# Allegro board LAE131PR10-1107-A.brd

Outline 326.8 x 119.05 mm; copper layers: TOP, GND1, IN1, VCC, IN2, IN3, GND2, BOTTOM. Coordinates in mm from the lower left corner of the outline.

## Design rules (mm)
constraint set DEFAULT: min track width 0.102
net group BC BUS_12/15: nets BC_CLK_ECE1117 BC_DAT_ECE1117
net group CLK_ITPXDP__R: nets CLK_ITPXDP_N_R CLK_ITPXDP_P_R
net group CODEC-SENSE_10: nets AUD_HP_NB_SENSE AUD_SENSE_A
net group CPU_DP1_0_C: nets CPU_DP1_N0_C CPU_DP1_P0_C
net group CPU_DP1_1_C: nets CPU_DP1_N1_C CPU_DP1_P1_C
net group CPU_DP1_2_C: nets CPU_DP1_N2_C CPU_DP1_P2_C
net group CPU_DP1_3_C: nets CPU_DP1_N3_C CPU_DP1_P3_C
net group CPU_DP1_AUX_C: nets CPU_DP1_AUXN_C CPU_DP1_AUXP_C
net group CPU_DP3_AUXN: nets CPU_DP3_AUXN CPU_DP3_AUXP
net group DIFFPAIR20: nets USB20_N2_R USB20_P2_R
net group DIFFPAIR23: nets TBT_I2C_SCL TBT_I2C_SDA
net group DIFFPAIR24: nets TBTA_LSRX_R TBTA_LSTX_R
net group DIFFPAIR25: nets TBTA_LSRX TBTA_LSTX
net group EDP_TX2: nets EDP_TXN2 EDP_TXP2
net group EDP_TX2_C: nets EDP_TXN2_C EDP_TXP2_C
net group EDP_TX3: nets EDP_TXN3 EDP_TXP3
net group EDP_TX3_C: nets EDP_TXN3_C EDP_TXP3_C
net group HDMI_12_15: nets CPU_DP1_AUXN CPU_DP1_AUXP
net group ISUMN_GT: nets ISUMN_GT ISUMP_GT
net group ISUMN_IA: nets ISUMN_IA ISUMP_IA
net group MSDATA: nets MSCLK MSDATA
net group PCIE_PRX_C_DTX_5: nets PCIE_PRX_C_DTX_N5 PCIE_PRX_C_DTX_P5
net group PCIE_PRX_C_DTX_6: nets PCIE_PRX_C_DTX_N6 PCIE_PRX_C_DTX_P6
net group PCIE_PRX_C_DTX_7: nets PCIE_PRX_C_DTX_N7 PCIE_PRX_C_DTX_P7
net group PCIE_PRX_C_DTX_8: nets PCIE_PRX_C_DTX_N8 PCIE_PRX_C_DTX_P8
net group PCIE_PRX_DTX_4: nets PCIE_PRX_DTX_N4 PCIE_PRX_DTX_P4
net group PCIE_PRX_DTX_7: nets PCIE_PRX_DTX_N7 PCIE_PRX_DTX_P7
net group PCIE_PRX_DTX_8: nets PCIE_PRX_DTX_N8 PCIE_PRX_DTX_P8
net group PCIE_PTX_C_DRX_4: nets PCIE_PTX_C_DRX_N4 PCIE_PTX_C_DRX_P4
net group PCIE_PTX_C_DRX_7: nets PCIE_PTX_C_DRX_N7 PCIE_PTX_C_DRX_P7
net group PCIE_PTX_C_DRX_8: nets PCIE_PTX_C_DRX_N8 PCIE_PTX_C_DRX_P8
net group PCIE_PTX_DRX_4: nets PCIE_PTX_DRX_N4 PCIE_PTX_DRX_P4
net group PCIE_PTX_DRX_7: nets PCIE_PTX_DRX_N7 PCIE_PTX_DRX_P7
net group PCIE_PTX_DRX_8: nets PCIE_PTX_DRX_N8 PCIE_PTX_DRX_P8
net group PCIE_RCOMP: nets PCIE_RCOMPN PCIE_RCOMPP
net group SATA_12: nets PCIE_PRX_DTX_P11 PCIE_PRX_DTX_P12
net group SD/MMCDAT0/RCLK+_R: nets SD/MMCDAT0/RCLK+_R SD/MMCDAT1/RCLK-_R
net group TBTA_AUX: nets TBTA_AUXN TBTA_AUXP
net group TBTA_AUX_C: nets TBTA_AUXN_C TBTA_AUXP_C
net group TBTA_USB20_: nets TBTA_USB20_N TBTA_USB20_P
net group USB3_PRX_L_DTX_2: nets USB3_PRX_L_DTX_N2 USB3_PRX_L_DTX_P2
net group USB3_PTX_L_DRX_2: nets USB3_PTX_L_DRX_N2 USB3_PTX_L_DRX_P2
net group USB20_4_L: nets USB20_N4_L USB20_P4_L
net group USB20_5_R: nets USB20_N5_R USB20_P5_R
net group USB20_7_L: nets USB20_N7_L USB20_P7_L
net group USB20_8_R: nets USB20_N8_R USB20_P8_R
net group VSA_SEN+: nets VSA_SEN+ VSA_SEN-
net group AR DDI_12_15: nets CPU_DP1_N0 CPU_DP1_N1 CPU_DP1_N2 CPU_DP1_N3 CPU_DP1_P0 CPU_DP1_P1 CPU_DP1_P2 CPU_DP1_P3
net group AR TBT: nets TBTA_HPD
net group AR TBT90H: nets TBTA_RX1N TBTA_RX1P TBTA_RX2N TBTA_RX2P TBTA_TX1N TBTA_TX1N_C TBTA_TX1P TBTA_TX1P_C TBTA_TX2N TBTA_TX2N_C TBTA_TX2P TBTA_TX2P_C
net group AR-HDMI: nets AR_DP1_N0 AR_DP1_N1 AR_DP1_N2 AR_DP1_N3 AR_DP1_P0 AR_DP1_P1 AR_DP1_P2 AR_DP1_P3 HDMI_CLKN HDMI_CLKP HDMI_L_CLKN HDMI_L_CLKP HDMI_L_TX_N0 HDMI_L_TX_N1 HDMI_L_TX_N2 HDMI_L_TX_P0 HDMI_L_TX_P1 HDMI_L_TX_P2 HDMI_TX_N0 HDMI_TX_N1 HDMI_TX_N2 HDMI_TX_P0 HDMI_TX_P1 HDMI_TX_P2
net group ASYN-COMP: nets CFG_RCOMP CPU_POPIRCOMP EDP_COMP EDRAM_OPIO_RCOMP EMMC_RCOMP EOPIO_RCOMP PCH_POPIRCOMP SD_RCOMP SM_RCOMP0 SM_RCOMP1 SM_RCOMP2 USBCOMP
net group ASYN_12: nets H_CATERR# H_CPUPWRGD H_CPUPWRGD_R H_PROCHOT# H_PROCHOT#_R H_THERMTRIP# H_VCCST_PWRGD_XDP PCH_PLTRST# PCH_PLTRST#_5105 PCH_PLTRST#_AND PCH_PLTRST#_EC PECI_EC PECI_EC_R PLTRST_LAN# PLTRST_TPM# THERMATRIP2# VCCST_PWRGD XDP_OBS0 XDP_OBS0_R XDP_OBS1 XDP_OBS1_R XDP_OBS2_R
net group ASYN_20: nets +DDR_VREF_A_DQ +DDR_VREF_B_DQ +DDR_VREF_CA DDR_DRAMRST# DDR_DRAMRST#_R
net group CARD-S_12: nets SD/MMCCD# SD/MMCCLK SD/MMCCLK_R SD/MMCCMD SD/MMCCMD_R SD/MMCDAT2 SD/MMCDAT2_R SD/MMCDAT3 SD/MMCDAT3_R SDWP
net group CARD_20: nets SD/MMCDAT0/RCLK+ SD/MMCDAT1/RCLK- SD_UHS2_D0N SD_UHS2_D0P SD_UHS2_D1N SD_UHS2_D1P
net group CLK-S_15: nets CLKREQ_PCIE#0 CPU_XDP_TCLK DMIC_CLK0 DMIC_CLK_CODEC HDA_BIT_CLK HDA_BIT_CLK_R JTAG_CLK PCH_JTAG_TCK PCI_CLK_LPC1 SUSCLK SUSCLK_R WIGIG_32KHZ XCLK_BIASREF XDP_JTAGX
net group CLK_ITPXDP_N: nets CLK_ITPXDP_P
net group CODEC-HP_10: nets AUD_HP_OUT_L AUD_HP_OUT_L1 AUD_HP_OUT_R AUD_HP_OUT_R1
net group CODEC_10: nets RING2 RING2_R SLEEVE SLEEVE_R
net group CONTROL LINK SIGNAL: nets PCH_CL_CLK1 PCH_CL_DATA1 PCH_CL_RST1#
net group CRITICAL S_15: nets INTRUDER# PCH_DPWROK PCH_PCIE_WAKE# PCH_PWROK PCH_RSMRST# PCIE_WAKE# PCIE_WAKE#_R SIO_PWRBTN# SIO_RCIN# SIO_RCIN#_EC SYS_RESET# SYS_RESET#_R
net group DDR-ALERT: nets DDR_A_ALERT#
net group DDRA-CLK: nets DDR_A_CLK0 DDR_A_CLK1 DDR_A_CLK#0 DDR_A_CLK#1
net group DDRA-CMD: nets DDR_A_ACT# DDR_A_BA0 DDR_A_BA1 DDR_A_BG0 DDR_A_BG1 DDR_A_MA0 DDR_A_MA1 DDR_A_MA2 DDR_A_MA3 DDR_A_MA4 DDR_A_MA5 DDR_A_MA6 DDR_A_MA7 DDR_A_MA8 DDR_A_MA9 DDR_A_MA10 DDR_A_MA11 DDR_A_MA12 DDR_A_MA13 DDR_A_MA14 DDR_A_MA15 DDR_A_MA16 DDR_A_PARITY
net group DDRA-CTL: nets DDR_A_CS#0 DDR_A_CS#1 DDR_A_ODT0 DDR_A_ODT1
net group DDRA-D0: nets DDR_A_D0 DDR_A_D1 DDR_A_D2 DDR_A_D3 DDR_A_D4 DDR_A_D5 DDR_A_D6 DDR_A_D7
net group DDRA-D1: nets DDR_A_D8 DDR_A_D9 DDR_A_D10 DDR_A_D11 DDR_A_D12 DDR_A_D13 DDR_A_D14 DDR_A_D15
net group DDRA-D2: nets DDR_A_D16 DDR_A_D17 DDR_A_D18 DDR_A_D19 DDR_A_D20 DDR_A_D21 DDR_A_D22 DDR_A_D23
net group DDRA-D3: nets DDR_A_D24 DDR_A_D25 DDR_A_D26 DDR_A_D27 DDR_A_D28 DDR_A_D29 DDR_A_D30 DDR_A_D31
net group DDRA-D4: nets DDR_A_D32 DDR_A_D33 DDR_A_D34 DDR_A_D35 DDR_A_D36 DDR_A_D37 DDR_A_D38 DDR_A_D39
net group DDRA-D5: nets DDR_A_D40 DDR_A_D41 DDR_A_D42 DDR_A_D43 DDR_A_D44 DDR_A_D45 DDR_A_D46 DDR_A_D47
net group DDRA-D6: nets DDR_A_D48 DDR_A_D49 DDR_A_D50 DDR_A_D51 DDR_A_D52 DDR_A_D53 DDR_A_D54 DDR_A_D55
net group DDRA-D7: nets DDR_A_D56 DDR_A_D57 DDR_A_D58 DDR_A_D59 DDR_A_D60 DDR_A_D61 DDR_A_D62 DDR_A_D63
net group DDRA-DQS: nets DDR_A_DQS0 DDR_A_DQS1 DDR_A_DQS2 DDR_A_DQS3 DDR_A_DQS4 DDR_A_DQS5 DDR_A_DQS6 DDR_A_DQS7 DDR_A_DQS#0 DDR_A_DQS#1 DDR_A_DQS#2 DDR_A_DQS#3 DDR_A_DQS#4 DDR_A_DQS#5 DDR_A_DQS#6 DDR_A_DQS#7
net group DDRA_CKE: nets DDR_A_CKE0 DDR_A_CKE1 DDR_A_CKE2 DDR_A_CKE3
net group DDRB-CLK: nets DDR_B_CLK0 DDR_B_CLK1 DDR_B_CLK#0 DDR_B_CLK#1
net group DDRB-CMD: nets DDR_B_ACT# DDR_B_BA0 DDR_B_BA1 DDR_B_BG0 DDR_B_BG1 DDR_B_MA0 DDR_B_MA1 DDR_B_MA2 DDR_B_MA3 DDR_B_MA4 DDR_B_MA5 DDR_B_MA6 DDR_B_MA7 DDR_B_MA8 DDR_B_MA9 DDR_B_MA10 DDR_B_MA11 DDR_B_MA12 DDR_B_MA13 DDR_B_MA14 DDR_B_MA15 DDR_B_MA16 DDR_B_PARITY
net group DDRB-CTL: nets DDR_B_CS#0 DDR_B_CS#1 DDR_B_ODT0 DDR_B_ODT1
net group DDRB-D0: nets DDR_B_D0 DDR_B_D1 DDR_B_D2 DDR_B_D3 DDR_B_D4 DDR_B_D5 DDR_B_D6 DDR_B_D7
net group DDRB-D1: nets DDR_B_D8 DDR_B_D9 DDR_B_D10 DDR_B_D11 DDR_B_D12 DDR_B_D13 DDR_B_D14 DDR_B_D15
net group DDRB-D2: nets DDR_B_D16 DDR_B_D17 DDR_B_D18 DDR_B_D19 DDR_B_D20 DDR_B_D21 DDR_B_D22 DDR_B_D23
net group DDRB-D3: nets DDR_B_D24 DDR_B_D25 DDR_B_D26 DDR_B_D27 DDR_B_D28 DDR_B_D29 DDR_B_D30 DDR_B_D31
net group DDRB-D4: nets DDR_B_D32 DDR_B_D33 DDR_B_D34 DDR_B_D35 DDR_B_D36 DDR_B_D37 DDR_B_D38 DDR_B_D39
net group DDRB-D5: nets DDR_B_D40 DDR_B_D41 DDR_B_D42 DDR_B_D43 DDR_B_D44 DDR_B_D45 DDR_B_D46 DDR_B_D47
net group DDRB-D6: nets DDR_B_D48 DDR_B_D49 DDR_B_D50 DDR_B_D51 DDR_B_D52 DDR_B_D53 DDR_B_D54 DDR_B_D55
net group DDRB-D7: nets DDR_B_D56 DDR_B_D57 DDR_B_D58 DDR_B_D59 DDR_B_D60 DDR_B_D61 DDR_B_D62 DDR_B_D63
net group DDRB-DQS: nets DDR_B_DQS0 DDR_B_DQS1 DDR_B_DQS2 DDR_B_DQS3 DDR_B_DQS4 DDR_B_DQS5 DDR_B_DQS6 DDR_B_DQS7 DDR_B_DQS#0 DDR_B_DQS#1 DDR_B_DQS#2 DDR_B_DQS#3 DDR_B_DQS#4 DDR_B_DQS#5 DDR_B_DQS#6 DDR_B_DQS#7
net group DDRB_ALERT: nets DDR_B_ALERT#
net group DDRB_CKE: nets DDR_B_CKE0 DDR_B_CKE1 DDR_B_CKE2 DDR_B_CKE3
net group DP-DDI2_15: nets CPU_DP2_AUXN CPU_DP2_AUXN_C CPU_DP2_AUXP CPU_DP2_AUXP_C CPU_DP2_N0 CPU_DP2_N0_C CPU_DP2_N1 CPU_DP2_N1_C CPU_DP2_N2 CPU_DP2_N2_C CPU_DP2_N3 CPU_DP2_N3_C CPU_DP2_P0 CPU_DP2_P0_C CPU_DP2_P1 CPU_DP2_P1_C CPU_DP2_P2 CPU_DP2_P2_C CPU_DP2_P3 CPU_DP2_P3_C SW2_DP1_AUXN SW2_DP1_AUXN_C SW2_DP1_AUXP SW2_DP1_AUXP_C SW2_DP1_N0 SW2_DP1_N0_C SW2_DP1_N1 SW2_DP1_N1_C SW2_DP1_N2 SW2_DP1_N2_C SW2_DP1_N3 SW2_DP1_N3_C SW2_DP1_P0 SW2_DP1_P0_C SW2_DP1_P1 SW2_DP1_P1_C SW2_DP1_P2 SW2_DP1_P2_C SW2_DP1_P3 SW2_DP1_P3_C SW2_DP2_AUXN SW2_DP2_AUXN_C SW2_DP2_AUXP SW2_DP2_AUXP_C SW2_DP2_N0 SW2_DP2_N0_C SW2_DP2_N1 SW2_DP2_N1_C SW2_DP2_N2 SW2_DP2_N2_C SW2_DP2_N3 SW2_DP2_N3_C SW2_DP2_P0 SW2_DP2_P0_C SW2_DP2_P1 SW2_DP2_P1_C SW2_DP2_P2 SW2_DP2_P2_C SW2_DP2_P3 SW2_DP2_P3_C
net group EDP_15: nets EDP_AUXN EDP_AUXN_C EDP_AUXP EDP_AUXP_C EDP_TXN0 EDP_TXN0_C EDP_TXN1 EDP_TXN1_C EDP_TXP0 EDP_TXP0_C EDP_TXP1 EDP_TXP1_C
net group EMC_50H: nets CORE_SNUB CORE_SW FAN1_PWM FAN1_TACH LX_1.8VALW LX_1V_PRIM LX_1VS_VCCIO LX_VCC_EDRAM LX_VCC_EOPIO SNUB_1.8VALW SNUB_1V_PRIM SNUB_1VS_VCCIO SNUB_VCC_EDRAM SNUB_VCC_EOPIO
net group EMI: nets BIA_PWM BIA_PWM_EC BST_3V BST_5V CLKRUN# EDP_BIA_PWM HOST_DEBUG_TX TP_LAN_JTAG_TCK
net group ESD-GND: nets CPU_XDP_PRDY# CPU_XDP_PREQ# CPU_XDP_TDI CPU_XDP_TDO CPU_XDP_TMS CPU_XDP_TRST# ME_RESET# PCH_JTAG_TDI PCH_JTAG_TDO PCH_JTAG_TMS POWER_SW#_MB POWER_SW_IN# RUNPWROK SIO_SLP_A# XDP_DBRESET#
net group ESD-NOCROSS-MOAT: nets CFG0 CFG1 CFG2 CFG3 CFG4 CFG5 CFG6 CFG7 CFG8 CFG9 CFG10 CFG11 CFG12 CFG13 CFG14 CFG15 CFG16 CFG17 CFG18 CFG19 ITP_PMODE SIO_EXT_SMI# USB_OC3#
net group ESPI: nets ESPI_ALERT# ESPI_CLK ESPI_CLK_5105 ESPI_CS# ESPI_IO0 ESPI_IO0_R ESPI_IO1 ESPI_IO1_R ESPI_IO2 ESPI_IO2_R ESPI_IO3 ESPI_IO3_R ESPI_RESET# SLOT2_CONFIG_0 SLOT2_CONFIG_1 SLOT2_CONFIG_2 SLOT2_CONFIG_3
net group GREENCLK_20: nets MEC_XTAL1 MEC_XTAL2 MEC_XTAL2_R PCH_RTCRST# PCH_RTCX1 PCH_RTCX2 PCH_RTCX2_R SRTCRST# XTAL24_IN XTAL_25_IN XTAL_25_OUT XTAL_25_OUT_R XTALO_R
net group HDA_5_15: nets DMIC0 HDA_RST# HDA_RST#_R HDA_SDIN0 HDA_SDIN0_R HDA_SDOUT HDA_SDOUT_R HDA_SYNC HDA_SYNC_R
net group I2C_15: nets ISH_I2C2_SCL ISH_I2C2_SCL_R ISH_I2C2_SDA ISH_I2C2_SDA_R
net group MDI_20: nets LAN_MDIN0 LAN_MDIN0_L LAN_MDIN1 LAN_MDIN1_L LAN_MDIN2 LAN_MDIN2_L LAN_MDIN3 LAN_MDIN3_L LAN_MDIP0 LAN_MDIP0_L LAN_MDIP1 LAN_MDIP1_L LAN_MDIP2 LAN_MDIP2_L LAN_MDIP3 LAN_MDIP3_L
net group PCIE_12: nets PCIE_PRX_C_DTX_N1 PCIE_PRX_C_DTX_N9 PCIE_PRX_C_DTX_P1 PCIE_PRX_C_DTX_P9 PCIE_PRX_DTX_N1 PCIE_PRX_DTX_N3 PCIE_PRX_DTX_N5 PCIE_PRX_DTX_N6 PCIE_PRX_DTX_N9 PCIE_PRX_DTX_N11 PCIE_PRX_DTX_N12 PCIE_PRX_DTX_P1 PCIE_PRX_DTX_P3 PCIE_PRX_DTX_P5 PCIE_PRX_DTX_P6 PCIE_PRX_DTX_P9 PCIE_PTX_C_DRX_N1 PCIE_PTX_C_DRX_N3 PCIE_PTX_C_DRX_N5 PCIE_PTX_C_DRX_N6 PCIE_PTX_C_DRX_N9 PCIE_PTX_C_DRX_N11 PCIE_PTX_C_DRX_N12 PCIE_PTX_C_DRX_P1 PCIE_PTX_C_DRX_P3 PCIE_PTX_C_DRX_P5 PCIE_PTX_C_DRX_P6 PCIE_PTX_C_DRX_P9 PCIE_PTX_C_DRX_P11 PCIE_PTX_C_DRX_P12 PCIE_PTX_DRX_N1 PCIE_PTX_DRX_N3 PCIE_PTX_DRX_N5 PCIE_PTX_DRX_N6 PCIE_PTX_DRX_N9 PCIE_PTX_DRX_N11 PCIE_PTX_DRX_N12 PCIE_PTX_DRX_P1 PCIE_PTX_DRX_P3 PCIE_PTX_DRX_P5 PCIE_PTX_DRX_P6 PCIE_PTX_DRX_P9 PCIE_PTX_DRX_P11 PCIE_PTX_DRX_P12
net group PLAT-CLK_12: nets CLK_ITPXDP_N CLK_PCIE_N0 CLK_PCIE_N1 CLK_PCIE_N2 CLK_PCIE_N3 CLK_PCIE_N4 CLK_PCIE_N5 CLK_PCIE_P0 CLK_PCIE_P1 CLK_PCIE_P2 CLK_PCIE_P3 CLK_PCIE_P4 CLK_PCIE_P5 CLKREQ_PCIE#1 CLKREQ_PCIE#2 CLKREQ_PCIE#3 CLKREQ_PCIE#4 CLKREQ_PCIE#5 XTAL24_OUT XTAL24_OUT_R
net group PWR_SRC: nets +PWR_SRC
net group RJ45_20: nets RJ45_MDIN0 RJ45_MDIN1 RJ45_MDIN2 RJ45_MDIN3 RJ45_MDIP0 RJ45_MDIP1 RJ45_MDIP2 RJ45_MDIP3
net group S20: nets +PWR_SRC_AC +SDC_IN TBTA_BOT_N TBTA_BOT_N_R TBTA_BOT_P TBTA_BOT_P_R TBTA_TOP_N TBTA_TOP_N_R TBTA_TOP_P TBTA_TOP_P_R XTALI XTALO
net group SD-NOCROSS-MOAT: nets JTAG_RST# ME_SUS_PWR_ACK SUSACK# USB_OC0# USB_OC1# USB_OC2#
net group SENSE_25: nets VCC_GT_SENSE VCCIO_SENSE VCCSENSE VSS_GT_SENSE VSSIO_SENSE VSSSENSE
net group SIM_15: nets UIM_CLK UIM_DATA UIM_RESET
net group SMB_15: nets CLK_TP_SIO_I2C_DAT CLK_TP_SIO_R CPU_DP1_CTRL_CLK CPU_DP1_CTRL_DATA CPU_DP2_CTRL_CLK CPU_DP2_CTRL_DATA DDR_XDP_WAN_SMBCLK DDR_XDP_WAN_SMBDAT HDMI_CTRL_CLK HDMI_CTRL_DATA MEM_SMBCLK MEM_SMBDATA PBAT_SMBCLK_C PBAT_SMBDAT_C SML0_SMBCLK SML0_SMBDATA SML1_SMBCLK SML1_SMBDATA USH_SMBCLK USH_SMBDAT
net group SPI-CLK_15: nets PCH_SPI_CLK PCH_SPI_CLK_0_R PCH_SPI_CLK_1_R PCH_SPI_CLK_2_R PCH_SPI_CLK_R1 TBT_ROM_CLK
net group SPI-S_5: nets PCH_SPI_CS#0 PCH_SPI_CS#0_R1 PCH_SPI_CS#0_R2 PCH_SPI_CS#1 PCH_SPI_CS#1_R1 PCH_SPI_CS#1_R2 PCH_SPI_CS#2 PCH_SPI_CS#2_R PCH_SPI_D0 PCH_SPI_D0_0_R PCH_SPI_D0_1_R PCH_SPI_D0_2_R PCH_SPI_D0_R1 PCH_SPI_D1 PCH_SPI_D1_0_R PCH_SPI_D1_1_R PCH_SPI_D1_2_R PCH_SPI_D1_R1 PCH_SPI_D2 PCH_SPI_D2_0_R PCH_SPI_D2_1_R PCH_SPI_D2_R1 PCH_SPI_D3 PCH_SPI_D3_0_R PCH_SPI_D3_1_R PCH_SPI_D3_R1 PCH_SPI_DO2_XDP PCH_SPI_DO_XDP RESET_OUT#_R
net group SPK_20: nets INT_SPK_L+ INT_SPK_L- INT_SPK_R+ INT_SPK_R- INT_SPKR_L+ INT_SPKR_L- INT_SPKR_R+ INT_SPKR_R-
net group SVID_12: nets H_CPU_SVIDALRT# VIDALERT_N VIDSCLK VIDSOUT
net group THERMAL_20: nets REM_DIODE1_N REM_DIODE1_P REM_DIODE2_N REM_DIODE2_P REM_DIODE4_N REM_DIODE4_P
net group USB20_12: nets SW_USB20_N1 SW_USB20_P1 USB20_N1 USB20_N1_R USB20_N2 USB20_N3 USB20_N3_R USB20_N4 USB20_N5 USB20_N7 USB20_N8 USB20_N10 USB20_P1 USB20_P1_R USB20_P2 USB20_P3 USB20_P3_R USB20_P4 USB20_P5 USB20_P7 USB20_P8 USB20_P10
net group USB30_12: nets USB3_PRX_DTX_N1 USB3_PRX_DTX_N2 USB3_PRX_DTX_N3 USB3_PRX_DTX_N4 USB3_PRX_DTX_P1 USB3_PRX_DTX_P2 USB3_PRX_DTX_P3 USB3_PRX_DTX_P4 USB3_PTX_C_DRX_N1 USB3_PTX_C_DRX_N2 USB3_PTX_C_DRX_N3 USB3_PTX_C_DRX_N4 USB3_PTX_C_DRX_P1 USB3_PTX_C_DRX_P2 USB3_PTX_C_DRX_P3 USB3_PTX_C_DRX_P4 USB3_PTX_DRX_N1 USB3_PTX_DRX_N2 USB3_PTX_DRX_N3 USB3_PTX_DRX_N4 USB3_PTX_DRX_P1 USB3_PTX_DRX_P2 USB3_PTX_DRX_P3 USB3_PTX_DRX_P4
net group W10: nets BAT1_LED# BAT2_LED# BATT_WHITE# BATT_YELLOW#
nets with their own width: min track width 0.203; nets TBTA_CC1 TBTA_CC2
nets with their own width: min track width 0.254; nets +1.0VO_DSW +3.3V_SPI +5V_ALWP +VCC_SA
nets with their own width: min track width 0.381; nets +SDREG2 HP_OUT_L HP_OUT_R
nets with their own width: min track width 0.508; nets +0.9V_LAN +1.0V_AMPHYPLL +1.0V_APLL +1.0V_APLLEBB +1.0V_CLK1 +1.0V_CLK2 +1.0V_CLK3 +1.0V_CLK4 +1.0V_CLK5 +1.0V_CLK6 +1.0V_DTS +1.0V_MPHYAON +1.0V_PRIM +1.0V_PRIM_CORE +1.0V_PRIM_XDP +1.0V_VCCST +1.0V_VCCST_C +1.0V_VCCSTG +1.2V_LDO +1.8V_RUN_CARD +3.3V_ALW +3.3V_ALW2 +3.3V_ALW_DSW +3.3V_ALW_UE1 +3.3V_ALWP +3.3V_CAM +3.3V_RTC_LDO +3.3V_RUN +3.3V_RUN_AUDIO +3.3V_RUN_UZ3 +3.3V_TP +5V_ALW +5V_ALW2 +COINCELL +DC_IN +DC_IN_SS +DDR_VREF_A_CA +PBATT +PECI_VREF +RSVD_VCC3P3_1 +RTC_CELL +RTC_CELL_VBAT +SIM_PWR +VCC_CORE +VCC_CORE_G0 +VCC_CORE_G1 +VCC_GT +VCHGR +VDDA_AVDD1 +VR_CAP +Z4012 GND GNDA Z2805 Z2806 Z2807 Z2808
nets with their own width: min track width 0.762; nets +1.0V_SRAM +3.3V_LAN_OUT
nets with their own width: min track width 1.016; nets +1.0VS_VCCIO +1.8V_PGPPF +1.8V_PRIM +3.3V_1.8V_PGPPG +3.3V_ALW_PCH +3.3V_LAN +3.3V_LAN_UZ2 +3.3V_PGPPB +3.3V_PGPPC +3.3V_PGPPD +3.3V_PGPPE +3.3V_RUN_CARD +5V_RUN_AUDIO +5V_TSP +GND_CHASSIS
nets with their own width: min track width 1.27; nets +3.3V_MMI_IN
nets with their own width: min track width 1.524; nets +3.3V_1.8V_PGPPA +EDP_VDD +LCDVDD
nets with their own width: min track width 2.032; nets +1.0V_MPHYGT +3.3V_WLAN +3.3V_WWAN_UZ4 +5V_RUN +BL_PWR_SRC +VHDMI_VCC
nets with their own width: min track width 2.54; nets +3.3V_WWAN +5V_USB_CHG_PWR

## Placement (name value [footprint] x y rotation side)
CA1  -  [C_0402]  304.97 21.51 270 top
CA2  -  [C_0402]  305.5 14.46 270 top
CA3  -  [C_0402]  305.53 16.15 90 top
CA4  -  [C_0402]  305.02 18.87 270 top
CA5  -  [C_0402]  62.11 115.09 0 top
CA6  -  [C_0402]  58.99 115.09 0 top
CA7  -  [C_0201]  56.31 110.22 0 top
CA8  -  [C_0201]  305.41 27.78 0 top
CA9  -  [C_0603]  304.5 26.83 0 top
CA10  -  [C_0201]  295.28 35.4 180 top
CA12  -  [C_0402]  309.6 21.53 0 top
CA13  -  [C_0402]  310.49 18.61 180 top
CA19  -  [C_0402]  295.91 9.7 0 top
CA22  -  [C_0402]  300.94 9.67 0 top
CA23  -  [C_0402]  299.79 9.66 180 top
CA24  -  [C_0402]  294.76 9.68 180 top
CA25  -  [C_0603]  300.67 27.29 270 top
CA27  -  [C_0402]  296.61 26.1 0 top
CA28  -  [C_0402]  296.61 25.22 0 top
CA29  -  [C_0603]  306.71 36.8 180 top
CA31  -  [C_0603]  294.26 38.45 90 top
CA33  -  [C_0402]  293.33 32.61 180 top
CA35  -  [C_0402]  305.63 30.7 0 top
CA41  -  [C_0402]  297.11 27.96 270 top
CA43  -  [C_0603]  303.35 27.51 270 top
CA44  -  [C_0603]  302.14 27.51 270 top
CA45  -  [C_0201]  300.98 38 0 top
CA46  -  [C_0603]  301.12 39.21 90 top
CA47  -  [C_0201]  297.75 38.13 0 top
CA48  -  [C_0603]  297.7 40.61 90 top
CA49  -  [C_0603]  305.7 35.4 0 top
CA51  -  [C_0603]  305.58 28.73 0 top
CA52  -  [C_0603]  303.78 37.93 90 top
CA53  -  [C_0603]  293.32 31.27 180 top
CA54  -  [C_0402]  293.33 33.62 180 top
CA55  -  [C_0201]  295.53 29.69 90 top
CA56  -  [C_0603]  294.78 29.94 180 top
CA57  -  [C_0201]  304.42 37.18 180 top
CA58  -  [C_0603]  305.14 37.93 90 top
CA59  -  [C_0603]  296.43 40.86 90 top
CA60  -  [C_0201]  294.52 40.61 90 top
CA61  -  [C_0603]  295.16 36.29 180 top
CA62  -  [C_0402]  295.73 26.14 270 top
CA63  -  [C_0402]  295.4 40.86 90 top
CA64  -  [C_0402]  300 18.69 270 top
CA65  -  [C_0402]  302.52 41.5 0 top
CA66  -  [C_0402]  302.52 40.48 0 top
CA67  -  [C_0402]  290.97 24.74 180 top
CA68  -  [C_0402]  290.97 25.63 180 top
CA69  -  [C_0402]  306.2 37.94 90 top
CA72  -  [C_0402]  295.4 26.98 90 top
CC7  -  [C_0402]  160 76.84 270 bottom
CC8  -  [C_0402]  176.53 88.12 270 bottom
CC9  -  [C_0201]  180.22 92.23 0 bottom
CC10  -  [C_0201]  179.01 84.78 270 bottom
CC21  -  [C_0402]  124.88 96.57 180 bottom
CC22  -  [C_0402]  125.74 96.57 0 bottom
CC23  -  [C_0402]  152.05 73.29 0 top
CC24  -  [C_0402]  139.53 58.87 270 top
CC25  -  [C_0402]  142.88 59.15 270 top
CC26  -  [C_0402]  150.61 74.18 180 top
CC27  -  [C_0402]  137.33 54.82 270 top
CC28  -  [C_0201]  114.92 100.44 270 bottom
CC29  -  [C_0201]  89.21 99.66 90 bottom
CC30  -  [C_0201]  66.36 100.25 270 top
CC32  -  [C_0402]  115.65 100.6 270 bottom
CC33  -  [C_0402]  73.98 99.93 180 bottom
CC176  -  [C_0402]  128.62 60.29 270 top
CC177  -  [C_0402]  128.76 56.13 90 top
CC178  -  [C_0402]  112.28 57.31 90 top
CC179  -  [C_0402]  130.34 60.32 270 top
CC180  -  [C_0402]  111.74 76.81 0 top
CC183  -  [C_0402]  111.73 77.73 0 top
CC184  -  [C_0402]  111.74 75.92 0 top
CC187  -  [C_0402]  111.73 75.03 0 top
CC195  -  [C_0402]  136.19 91.91 90 bottom
CC199  -  [C_0402]  129.04 95.52 180 top
CC202  -  [C_0402]  132.57 82.29 180 top
CC203  -  [C_0402]  136.4 83.6 270 top
CC204  -  [C_0402]  146.42 73.48 90 top
CC205  -  [C_0402]  134.48 76.21 270 top
CC206  -  [C_0402]  133.84 77.86 90 top
CC207  -  [C_0402]  136.69 76.98 180 top
CC208  -  [C_0402]  136.49 78.7 0 top
CC209  -  [C_0402]  134.71 77.87 0 top
CC210  -  [C_0805]  143.94 99.52 90 top
CC211  -  [C_0402]  136.43 80.35 0 top
CC212  -  [C_0402]  146.56 76.69 270 top
CC213  -  [C_0201]  134.41 72.04 180 top
CC214  -  [C_0201]  137.38 71.16 90 top
CC215  -  [C_0402]  137.19 74.26 0 top
CC216  -  [C_0402]  140.4 97.25 0 top
CC217  -  [C_0402]  133.18 76.11 90 top
CC218  -  [C_0402]  134.43 80.12 180 top
CC220  -  [C_0805]  130.58 97.87 180 top
CC221  -  [C_0805]  140.1 99.13 0 bottom
CC222  -  [C_0402]  139.36 78.09 0 top
CC223  -  [C_0201]  140.71 75.38 0 top
CC224  -  [C_0402]  140.63 72.92 270 top
CC225  -  [C_0805]  143.86 95.4 90 top
CC226  -  [C_0805]  134.09 98.79 90 bottom
CC250  -  [C_0402]  128.82 74.18 90 top
CC251  -  [C_0402]  126.88 72.03 90 top
CC252  -  [C_0402]  128.64 72.86 180 top
CC253  -  [C_0402]  127.93 74.18 90 top
CC264  -  [C_0402]  138.33 82.94 0 top
CC265  -  [C_0402]  138.05 75.31 180 top
CC266  -  [C_0402]  140.43 56.1 0 top
CC269  -  [C_0402]  77.79 97.58 270 bottom
CC270  -  [C_0201]  141.23 56.99 180 top
CC279  -  [C_0603]  173.13 51.71 0 top
CC280  -  [C_0603]  173.13 50.45 0 top
CC281  -  [C_0201]  166.16 89.74 180 top
CC288  -  [C_0402]  131.56 73.54 180 top
CC289  -  [C_0402]  112 78.64 0 top
CC290  -  [C_0402]  110.43 79.61 90 top
CC291  -  [C_0402]  110.73 78.29 180 top
CC292  -  [C_0402]  110.44 76.8 180 top
CC293  -  [C_0402]  111.67 79.53 0 top
CC294  -  [C_0603]  110.14 57.08 180 top
CC295  -  [C_0603]  111.62 55.75 0 top
CC296  -  [C_0603]  131.11 56.14 180 top
CC297  -  [C_0402]  124.24 72.97 180 top
CC300  -  [C_0402]  99.03 94.32 90 bottom
CC301  -  [C_0402]  105.96 97.05 90 bottom
CC302  -  [C_0402]  318.53 101.75 180 bottom
CC303  -  [C_0402]  114.2 95.98 90 bottom
CC304  -  [C_0402]  112.73 93.71 90 bottom
CC305  -  [C_0402]  110.91 96.37 90 bottom
CC306  -  [C_0402]  65.48 106.39 180 top
CC307  -  [C_0402]  77.83 99.04 0 bottom
CC308  -  [C_0402]  109.98 96.49 90 bottom
CC310  -  [C_0402]  102.94 96.38 90 bottom
CC312  -  [C_0402]  107.72 95.42 0 bottom
CC313  -  [C_0201]  134.93 74.53 180 top
CC314  -  [C_0201]  147.08 96.24 180 top
CC316  -  [C_0402]  145.8 60.8 270 top
CC318  -  [C_0402]  167.3 80.38 0 top
CC319  -  [C_0402]  167.29 79.49 0 top
CC320  -  [C_0402]  148.06 83.93 180 top
CC321  -  [C_0402]  108.73 93.44 90 bottom
CC322  -  [C_0402]  132.65 55.1 90 top
CC323  -  [C_0402]  148.12 97.34 90 top
CC324  -  [C_0402]  135.38 75.24 0 top
CC325  -  [C_0402]  145.76 95.34 0 top
CC326  -  [C_0402]  153.27 72.04 270 bottom
CC331  -  [C_0402]  134.05 57.42 90 top
CC332  -  [C_0402]  135.57 61.32 270 top
CC333  -  [C_0402]  134.94 57.42 90 top
CD1  -  [C_0603]  81.17 33.66 270 top
CD2  -  [C_0603]  78.5 33.48 270 top
CD3  -  [C_0603]  75.64 24.49 90 top
CD4  -  [C_0603]  78.07 24.45 90 top
CD5  -  [C_0603]  82.39 33.67 270 top
CD6  -  [C_0603]  83.63 33.67 270 top
CD7  -  [C_0603]  84.88 33.66 270 top
CD8  -  [C_0603]  74.37 24.5 90 top
CD9  -  [C_0402]  54.35 33.59 270 top
CD10  -  [C_0402]  77.41 32.92 270 top
CD11  -  [C_0402]  73.48 32.96 270 top
CD12  -  [C_0402]  108.33 32.79 90 top
CD13  -  [C_0402]  76.97 24.49 90 top
CD14  -  [C_0402]  64.78 32.87 270 top
CD15  -  [C_0402]  79.61 32.99 270 top
CD16  -  [C_0402]  86.74 24.37 90 top
CD17  -  [C_D3]  82.63 37.86 0 top
CD18  -  [C_0402]  120.65 32.61 270 top
CD19  -  [C_0402]  121.54 32.61 270 top
CD20  -  [C_0603]  119.43 33.67 90 top
CD21  -  [C_0603]  120.65 33.67 90 top
CD22  -  [C_0603]  117.31 29.7 90 top
CD23  -  [C_0402]  118.39 30.02 90 top
CD24  -  [C_0402]  116.23 29.95 90 top
CD25  -  [C_0402]  88.33 24.52 90 top
CD26  -  [C_0402]  89.27 24.52 90 top
CD27  -  [C_0402]  110.33 32.28 90 top
CD28  -  [C_0201]  109.56 32.26 90 top
CD29  -  [C_0402]  69.46 27.91 90 top
CD31  -  [C_0402]  172.9 27.26 0 top
CD32  -  [C_0201]  88.52 61.3 270 bottom
CD33  -  [C_0603]  159.01 36.48 270 top
CD34  -  [C_0603]  166.85 36.54 270 top
CD35  -  [C_0603]  186.87 36.8 270 top
CD36  -  [C_0603]  181.55 27.08 0 top
CD37  -  [C_0603]  149.44 28.43 90 top
CD38  -  [C_0603]  154.22 28.19 90 top
CD39  -  [C_0603]  158.78 28.32 0 top
CD40  -  [C_0603]  164.89 36.59 270 top
CD41  -  [C_0402]  161.53 36.14 270 top
CD42  -  [C_0402]  157.91 35.94 270 top
CD43  -  [C_0402]  156.11 35.95 270 top
CD44  -  [C_0402]  161.24 28.11 90 top
CD45  -  [C_0402]  157.04 35.93 270 top
CD46  -  [C_0402]  155.18 35.95 270 top
CD47  -  [C_0402]  160.2 35.82 270 top
CD48  -  [C_0402]  163.4 35.93 270 top
CD49  -  [C_D3]  93.4 48.16 270 top
CD50  -  [C_0402]  194.01 35.41 0 top
CD51  -  [C_0402]  194.01 34.49 0 top
CD52  -  [C_0603]  193.87 33.37 0 top
CD53  -  [C_0603]  193.7 36.47 0 top
CD54  -  [C_0603]  192.32 28.39 0 top
CD55  -  [C_0402]  192.6 27.29 0 top
CD56  -  [C_0402]  192.53 29.44 0 top
CD57  -  [C_0402]  163.25 28.12 90 top
CD58  -  [C_0402]  164.14 28.12 90 top
CD59  -  [C_0402]  190.81 31.64 180 top
CD60  -  [C_0201]  190.81 32.38 180 top
CD61  -  [C_0402]  134.85 28.18 180 top
CD62  -  [C_0402]  165.06 29.04 270 top
CE1  -  [C_0402]  274.04 54.76 270 top
CE2  -  [C_0402]  274.98 54.76 270 top
CE3  -  [C_0402]  273.98 30.49 270 top
CE4  -  [C_0402]  273.13 32.98 270 top
CE5  -  [C_0402]  244.95 39.91 90 top
CE6  -  [C_0402]  244.95 42.61 270 top
CE8  -  [C_0402]  282.56 46.2 270 top
CE10  -  [C_0402]  250.07 32.99 180 top
CE11  -  [C_0201]  259.95 34.63 180 top
CE12  -  [C_0402]  251.91 31.07 270 top
CE13  -  [C_0201]  275.02 52.19 90 top
CE14  -  [C_0402]  274.63 51.02 0 top
CE15  -  [C_0201]  274.49 49.07 0 top
CE16  -  [C_0603]  264.73 30.24 90 top
CE17  -  [C_0603]  265.75 33.74 0 top
CE18  -  [C_0201]  266.16 34.69 0 top
CE19  -  [C_0201]  274.45 52.19 90 top
CE20  -  [C_0201]  274.47 49.69 0 top
CE21  -  [C_0201]  274.13 37.71 270 top
CE22  -  [C_0201]  277.12 37.59 270 top
CE23  -  [C_0201]  274.35 50.26 0 top
CE24  -  [C_0402]  260.2 42.3 270 top
CE25  -  [C_0201]  272.37 51.06 90 top
CE26  -  [C_0402]  259.72 44.13 270 top
CE27  -  [C_0402]  260.14 45.89 270 top
CE28  -  [C_0402]  257.23 31.48 270 top
CE29  -  [C_0402]  257.23 32.4 90 top
CE30  -  [C_0402]  264.94 50.5 180 top
CE31  -  [C_0402]  270.16 34.55 270 top
CE32  -  [C_0603]  184.54 77.63 90 bottom
CE35  -  [C_0402]  129.09 76.8 90 top
CE36  -  [C_0402]  242.52 38.86 270 bottom
CE37  -  [C_0402]  294.69 36.82 90 bottom
CE38  -  [C_0402]  262.1 52.28 90 top
CE39  -  [C_0402]  86.24 91.27 90 bottom
CE40  -  [C_0402]  269.22 49.19 90 top
CE46  -  [C_0402]  198.33 38.87 0 bottom
CE47  -  [C_0402]  257.06 57.71 270 top
CE52  -  [C_0402]  258.71 50.72 0 top
CE53  -  [C_0402]  258.8 55.42 180 top
CE54  -  [C_0402]  264.8 34.58 270 top
CE57  -  [C_0402]  253.05 39.27 180 top
CE59  -  [C_0402]  264.58 29.28 270 top
CE60  -  [C_0402]  277.57 43.8 0 top
CE61  -  [C_0402]  257.93 37.24 0 top
CE62  -  [C_0402]  263.6 31.15 90 top
CE500  -  [C_0402]  279.4 62.38 180 top
CE503  -  [C_0402]  257.58 87 0 top
CI1  -  [C_1206]  22.76 27.13 0 bottom
CI3  -  [C_0201]  22.14 28.48 90 bottom
CI4  -  [C_0402]  23.89 32.42 0 top
CI5  -  [C_0402]  23.89 31.53 0 top
CI6  -  [C_0603]  26.9 27.68 270 bottom
CI7  -  [C_0201]  27.95 27.77 270 bottom
CI8  -  [C_1206]  21.09 46.7 0 bottom
CI10  -  [C_0201]  23.43 44.08 270 top
CI11  -  [C_0603]  21.31 47.41 270 top
CI12  -  [C_0201]  22.27 47.44 270 top
CI13  -  [C_0402]  299.94 64.22 180 bottom
CI14  -  [C_1206]  301.37 56.74 270 bottom
CI16  -  [C_0402]  299.94 63.32 180 bottom
CI17  -  [C_0201]  301.22 57.69 180 bottom
CI19  -  [C_0201]  293.83 72.33 0 top
CI27  -  [C_0402]  26.6 42.73 0 top
CI28  -  [C_0402]  26.61 43.63 0 top
CI29  -  [C_0402]  277.67 71 0 top
CI30  -  [C_0402]  277.7 70.07 0 top
CI31  -  [C_0402]  294.08 73.07 0 top
CI32  -  [C_B2]  304.04 55.95 90 bottom
CI33  -  [C_0603]  291.7 69.14 180 top
CI34  -  [C_0603]  291.67 70.4 180 top
CI43  -  [C_0402]  305.23 60.54 90 top
CI44  -  [C_0402]  304.32 60.53 90 top
CI45  -  [C_0402]  23.85 28.58 90 bottom
CI46  -  [C_0402]  22.9 28.59 90 bottom
CI47  -  [C_0402]  21.59 44.62 270 top
CI48  -  [C_0402]  22.48 44.62 270 top
CL1  -  [C_0402]  269.38 96.83 0 top
CL2  -  [C_0402]  269.38 95.94 0 top
CL3  -  [C_0201]  276.05 88.8 0 top
CL4  -  [C_0603]  276.07 86.12 180 top
CL5  -  [C_0402]  269.38 94.99 0 top
CL6  -  [C_0402]  269.38 94.1 0 top
CL7  -  [C_0201]  280.42 91.66 0 top
CL8  -  [C_0201]  280.42 92.8 0 top
CL9  -  [C_0201]  280.42 96.74 0 top
CL10  -  [C_0201]  270.13 97.63 180 top
CL11  -  [C_0201]  279.66 89.41 270 top
CL12  -  [C_0603]  268.99 92.3 270 top
CL13  -  [C_0402]  278.3 87.12 180 top
CL14  -  [C_0402]  279.16 87.12 0 top
CL15  -  [C_0201]  296.38 86.71 0 top
CL16  -  [C_0201]  292.09 82.01 180 top
CL17  -  [C_0201]  292.1 83.28 180 top
CL18  -  [C_0402]  309.44 100.29 90 top
CL19  -  [C_0201]  310.2 100.26 90 top
CL20  -  [C_0201]  291.99 89.63 180 top
CL21  -  [C_0201]  292.11 90.9 180 top
CL22  -  [C_1808]  307.39 96.82 180 bottom
CL28  -  [C_0805]  272.01 87.46 270 top
CL29  -  [C_0402]  275.97 99.41 90 top
CL30  -  [C_0402]  280.16 94.33 0 top
CLIP1  -  [EMIST_SUL-12A2M_1P]  307.4 61.6 90 top
CLIP2  -  [EMIST_SUL-12A2M_1P]  314.6 70.65 0 top
CLIP3  -  [EMIST_SUL-12A2M_1P]  11.8 15.4 0 top
CLIP4  -  [EMIST_SUL-12A2M_1P]  18.45 35.4 90 top
CLIP5  -  [EMIST_SUL-12A2M_1P]  11.8 55.4 180 top
CLIP6  -  [EMIST_SUL-12A2M_1P]  314.6 52.55 0 top
CLIP7  -  [EMIST_SUL-12A2M_1P]  12.25 15.4 180 bottom
CLIP8  -  [EMIST_SUL-12A2M_1P]  18.45 35.4 270 bottom
CLIP9  -  [EMIST_SUL-12A2M_1P]  12.25 55.4 180 bottom
CLIP10  -  [EMIST_SUL-12A2M_1P]  314.15 52.55 180 bottom
CLIP11  -  [EMIST_SUL-12A2M_1P]  307.4 61.6 270 bottom
CLIP12  -  [EMIST_SUL-12A2M_1P]  314.15 70.65 180 bottom
CMOS1  -  [SHORTPADS-NPM]  165.78 73.92 90 bottom
CN60  -  [C_0402]  33.53 17.11 90 top
CN61  -  [C_0201]  26.67 19.65 180 top
CN62  -  [C_0201]  34.29 17.11 90 top
CN63  -  [C_0603]  21.4 16.86 90 top
CN64  -  [C_0603]  27.31 18.69 180 top
CN69  -  [C_0402]  29.92 19.23 90 bottom
CN70  -  [C_0402]  29.03 19.23 90 bottom
CN71  -  [C_0402]  26.34 19.26 90 bottom
CN72  -  [C_0402]  25.45 19.26 90 bottom
CR1  -  [C_0402]  298.83 56.09 90 top
CR2  -  [C_0201]  297.94 57.21 90 top
CR3  -  [C_0201]  297.22 48.1 180 top
CR4  -  [C_0402]  297.33 46.73 0 top
CR5  -  [C_0603]  294.43 49.12 180 top
CR6  -  [C_0201]  296.04 48.33 270 top
CR7  -  [C_0201]  299.15 47.81 270 top
CR11  -  [C_0402]  291.64 53.94 0 top
CR12  -  [C_0402]  291.64 53.05 0 top
CR13  -  [C_0402]  291.63 52.19 0 top
CR14  -  [C_0402]  291.61 51.31 0 top
CR15  -  [C_0402]  301.3 54.45 0 top
CR17  -  [C_0201]  308.21 39.64 90 top
CR18  -  [C_0603]  309.12 38.83 90 top
CR19  -  [C_0201]  317.32 48.63 180 top
CR20  -  [C_0603]  318.09 47.69 180 top
CR21  -  [C_0402]  302.91 47.73 270 top
CR22  -  [C_0402]  301.41 49.59 0 top
CR25  -  [C_0402]  297.33 44.95 0 top
CR26  -  [C_0402]  297.33 45.84 0 top
CR27  -  [C_0402]  300.61 56.09 90 top
CR28  -  [C_0402]  299.72 56.09 90 top
CT1  -  [C_0201]  24.64 74.01 270 bottom
CT2  -  [C_0201]  33.06 94.01 270 top
CT3  -  [C_0201]  33.63 94.01 270 top
CT4  -  [C_0201]  30.77 94.01 270 top
CT5  -  [C_0201]  31.35 94.01 270 top
CT6  -  [C_0201]  31.92 93.43 90 top
CT7  -  [C_0201]  32.49 93.43 90 top
CT8  -  [C_0201]  30.14 94.51 90 top
CT9  -  [C_0201]  29.57 94.51 90 top
CT10  -  [C_0201]  36.84 83.9 180 top
CT11  -  [C_0201]  36.84 84.47 180 top
CT12  -  [C_0201]  38.43 84.7 180 top
CT13  -  [C_0201]  38.43 85.27 180 top
CT14  -  [C_0201]  36.59 85.46 180 top
CT15  -  [C_0201]  36.59 86.04 180 top
CT16  -  [C_0201]  38.69 86.42 180 top
CT17  -  [C_0201]  38.69 86.99 180 top
CT18  -  [C_0201]  38.88 82.42 180 top
CT19  -  [C_0201]  38.88 81.84 180 top
CT20  -  [C_0402]  23.99 93.61 0 top
CT21  -  [C_0402]  21.39 93.59 180 top
CT25  -  [C_0201]  29.16 83.43 0 bottom
CT26  -  [C_0201]  28.72 84.89 0 bottom
CT27  -  [C_0201]  28.65 86.73 0 bottom
CT28  -  [C_0201]  31.75 87.56 180 bottom
CT29  -  [C_0201]  33.25 86.52 270 bottom
CT30  -  [C_0201]  27.94 84.06 270 bottom
CT31  -  [C_0201]  33.45 87.78 90 bottom
CT32  -  [C_0201]  31.1 88.66 90 bottom
CT33  -  [C_0201]  30 88.19 180 bottom
CT34  -  [C_0201]  28.53 91.18 180 bottom
CT35  -  [C_0201]  29.6 91.18 0 bottom
CT36  -  [C_0201]  29.6 91.76 0 bottom
CT37  -  [C_0201]  28.53 91.76 180 bottom
CT38  -  [C_0201]  30.47 86.19 90 bottom
CT39  -  [C_0201]  29.94 85.46 180 bottom
CT40  -  [C_0201]  31.13 84.89 0 bottom
CT41  -  [C_0201]  31.14 84.21 0 bottom
CT42  -  [C_0201]  26.03 83.59 180 bottom
CT43  -  [C_0201]  26.37 84.82 180 bottom
CT44  -  [C_0402]  21.82 81.54 270 top
CT45  -  [C_0402]  20.93 81.54 270 top
CT46  -  [C_0402]  20.04 81.54 270 top
CT47  -  [C_0402]  19.15 81.54 270 top
CT48  -  [C_0201]  26.79 87.08 90 bottom
CT49  -  [C_0201]  24.83 86.11 270 bottom
CT50  -  [C_0201]  24.2 86.11 270 bottom
CT51  -  [C_0201]  23.62 86.11 270 bottom
CT52  -  [C_0201]  22.99 86.11 270 bottom
CT53  -  [C_0201]  24.2 86.73 90 bottom
CT54  -  [C_0201]  24.83 86.73 90 bottom
CT55  -  [C_0603]  16.17 77.91 90 top
CT56  -  [C_0603]  18.58 77.91 90 top
CT57  -  [C_0603]  17.38 77.91 90 top
CT59  -  [C_0402]  21.41 92.71 180 top
CT60  -  [C_0402]  24.85 91.48 45 bottom
CT61  -  [C_0201]  25.94 88.66 180 bottom
CT62  -  [C_0201]  26.85 86.28 0 bottom
CT63  -  [C_0201]  27.4 89.53 180 bottom
CT64  -  [C_0201]  27.4 88.25 180 bottom
CT67  -  [C_0402]  18.9 84.78 270 bottom
CT68  -  [C_0805]  17.72 82.8 180 bottom
CT69  -  [C_0805]  17.72 84.51 180 bottom
CT70  -  [C_0402]  27.22 49.49 270 top
CT71  -  [C_0402]  30.04 66.44 90 top
CT72  -  [C_0402]  32.32 63.58 90 top
CT73  -  [C_0402]  24.89 65.42 90 top
CT74  -  [C_0402]  31.68 67.72 0 top
CT75  -  [C_0805]  21.91 57.17 90 bottom
CT76  -  [C_0805]  23.62 57.17 90 bottom
CT77  -  [C_0805]  21.02 55.96 270 bottom
CT78  -  [C_0805]  22.73 55.96 270 bottom
CT80  -  [C_0201]  25.58 69.21 270 top
CT81  -  [C_0201]  25.01 69.21 270 top
CT82  -  [C_0603]  25.41 55.89 180 top
CT83  -  [C_0402]  26.52 65.61 90 top
CT84  -  [C_0603]  28.07 66.33 90 top
CT85  -  [C_0402]  21.87 57.82 180 top
CT86  -  [C_0402]  21.85 58.85 180 top
CT87  -  [C_0402]  26.04 60.81 270 bottom
CT88  -  [C_0201]  18.16 95.04 270 top
CT89  -  [C_0402]  17.03 95.23 180 top
CT90  -  [C_0402]  19.62 93.69 270 top
CT91  -  [C_0603]  16.66 97.66 90 top
CT92  -  [C_0402]  16.78 96.6 180 top
CT93  -  [C_0402]  32.34 21.23 270 bottom
CT94  -  [C_0603]  22.51 98.06 0 bottom
CT95  -  [C_0201]  21.6 90.01 180 top
CT96  -  [C_0201]  21.6 89.44 180 top
CT97  -  [C_0201]  21.91 88.5 180 bottom
CT98  -  [C_0201]  21.91 89.07 180 bottom
CT99  -  [C_0201]  9.87 91.11 0 bottom
CT100  -  [C_0201]  8.79 93.29 90 bottom
CT101  -  [C_0201]  9.87 88.39 0 bottom
CT102  -  [C_0201]  9.87 87.8 0 bottom
CT123  -  [C_0201]  28.36 94.01 270 top
CT124  -  [C_0201]  28.93 94.01 270 top
CT125  -  [C_0201]  26.27 94.01 270 top
CT126  -  [C_0201]  26.84 94.01 270 top
CT127  -  [C_0201]  27.28 95.21 90 top
CT128  -  [C_0201]  27.85 95.21 90 top
CT129  -  [C_0201]  25.31 95.21 90 top
CT130  -  [C_0201]  25.88 95.21 90 top
CT168  -  [C_0201]  36.27 89.72 180 top
CT169  -  [C_0201]  39 90.05 180 top
CT170  -  [C_0201]  36.47 91.55 225 top
CT171  -  [C_0201]  38.05 88.84 180 top
CT172  -  [C_0201]  38.05 88.27 180 top
CT173  -  [C_0201]  36.09 92 225 top
CT174  -  [C_0201]  36.27 89.15 180 top
CT175  -  [C_0201]  39 90.62 180 top
CT176  -  [C_0201]  36.34 88.07 180 top
CT177  -  [C_0201]  36.34 87.5 180 top
CT189  -  [C_0402]  13.39 83.69 90 bottom
CT190  -  [C_0402]  14.31 83.69 90 bottom
CT201  -  [C_0201]  20.58 61.82 90 bottom
CT202  -  [C_0201]  20.58 65.63 90 bottom
CT203  -  [C_0201]  20.58 63.85 90 bottom
CT204  -  [C_0201]  20.7 67.53 90 bottom
CV1  -  [C_0402]  72.9 111.07 90 top
CV2  -  [C_0402]  73.79 111.07 90 top
CV3  -  [C_0402]  74.3 109.26 90 top
CV4  -  [C_0402]  75.19 109.26 90 top
CV5  -  [C_0402]  75.69 111.05 90 top
CV6  -  [C_0402]  76.58 111.05 90 top
CV7  -  [C_0402]  77.81 110.86 90 top
CV8  -  [C_0402]  78.7 110.86 90 top
CV9  -  [C_0402]  79.81 111.85 90 top
CV10  -  [C_0402]  80.7 111.85 90 top
CV11  -  [C_0603]  63.38 107.68 270 top
CV12  -  [C_0201]  70.13 116.59 180 top
CV13  -  [C_0402]  59.26 105.37 0 top
CV14  -  [C_0402]  59.31 103.6 0 top
CV15  -  [C_0603]  62.03 107.69 270 top
CV16  -  [C_0603]  71.13 115.64 180 top
CV17  -  [C_0402]  72.53 108.83 90 top
CV18  -  [C_0402]  98.86 116.4 0 top
CV19  -  [C_0402]  98.85 117.32 0 top
CV20  -  [C_0402]  72.37 116.38 0 top
CV21  -  [C_0402]  72.39 117.27 0 top
CV22  -  [C_0402]  62.11 113.23 0 top
CV23  -  [C_0402]  62.14 114.12 0 top
CV24  -  [C_0402]  62.42 108.73 90 top
CV25  -  [C_0402]  61.52 108.73 90 top
CV31  -  [C_0402]  19.86 61.73 180 bottom
CV32  -  [C_0402]  19.88 62.6 180 bottom
CV33  -  [C_0402]  19.86 65.5 180 bottom
CV34  -  [C_0402]  19.86 66.38 180 bottom
CV35  -  [C_0402]  19.85 63.72 180 bottom
CV36  -  [C_0402]  19.86 64.6 180 bottom
CV37  -  [C_0402]  18.99 67.37 0 bottom
CV38  -  [C_0402]  18.99 68.26 0 bottom
CV39  -  [C_0201]  19.31 75.02 0 bottom
CV40  -  [C_0201]  15.12 72.74 90 bottom
CV41  -  [C_0603]  16 72.4 90 bottom
CV81  -  [C_0402]  121.78 111.59 0 bottom
CV82  -  [C_0402]  121.74 112.48 0 bottom
CV83  -  [C_0201]  93.9 115.47 90 top
CV84  -  [C_0201]  108.71 105.57 270 bottom
CV85  -  [C_0201]  122.81 106.65 0 bottom
CV86  -  [C_0201]  118.21 103.43 90 bottom
CV87  -  [C_0201]  117.32 103.43 90 bottom
CV88  -  [C_0201]  116.44 103.24 90 bottom
CV89  -  [C_0201]  115.55 103.24 90 bottom
CV90  -  [C_0201]  114.78 102.8 90 bottom
CV91  -  [C_0201]  113.9 102.8 90 bottom
CV92  -  [C_0201]  113.2 102.74 90 bottom
CV93  -  [C_0201]  112.31 102.74 90 bottom
CV94  -  [C_0201]  106.89 104.18 90 bottom
CV95  -  [C_0201]  106 104.18 90 bottom
CV96  -  [C_0402]  111.46 104.91 270 bottom
CV145  -  [C_0402]  294.29 40.14 180 bottom
CV146  -  [C_0402]  294.27 41.05 180 bottom
CV147  -  [C_0402]  294.21 43.19 180 bottom
CV148  -  [C_0402]  294.2 42.28 180 bottom
CV149  -  [C_0402]  286.39 59.98 270 bottom
CV150  -  [C_0402]  287.28 59.98 270 bottom
CV152  -  [C_0402]  285.31 59.98 270 bottom
CV153  -  [C_0402]  284.42 59.98 270 bottom
CV156  -  [C_0402]  283.4 59.98 270 bottom
CV157  -  [C_0402]  282.51 59.98 270 bottom
CZ1  -  [C_0201]  62.18 112.49 0 top
CZ2  -  [C_0201]  98.91 115.6 0 top
CZ3  -  [C_0402]  101.54 116.24 0 top
CZ12  -  [C_0402]  292.14 43.62 180 bottom
CZ13  -  [C_0402]  292.11 44.53 180 bottom
CZ14  -  [C_0402]  291.19 49.68 180 bottom
CZ15  -  [C_0402]  291.15 50.59 180 bottom
CZ17  -  [C_0402]  259.49 75.72 90 top
CZ18  -  [C_0402]  263.59 75.72 90 top
CZ19  -  [C_0402]  262.65 75.71 90 top
CZ20  -  [C_0603]  261.55 75.76 90 top
CZ21  -  [C_0402]  260.4 75.71 90 top
CZ23  -  [C_0402]  279.3 76.61 90 top
CZ24  -  [C_0402]  278.39 76.63 90 top
CZ25  -  [C_0402]  280.25 76.63 90 top
CZ26  -  [C_B2]  285.5 70.94 90 bottom
CZ27  -  [C_0603]  282.86 36.18 0 top
CZ28  -  [C_0402]  279.64 54.06 90 top
CZ29  -  [C_0402]  280.58 54.01 90 top
CZ30  -  [C_0201]  282.69 38 0 top
CZ31  -  [C_0201]  283.17 52.28 0 top
CZ32  -  [C_0603]  281.68 34.58 270 top
CZ33  -  [C_0402]  283.07 53.02 0 top
CZ34  -  [C_0402]  281.5 54.01 90 top
CZ35  -  [C_0402]  280.61 34.51 270 top
CZ36  -  [C_0402]  282.78 37.23 0 top
CZ37  -  [C_0402]  304.3 45.69 0 bottom
CZ38  -  [C_0402]  304.11 42.67 0 bottom
CZ39  -  [C_0402]  304.14 40.6 0 bottom
CZ40  -  [C_0402]  301.5 46.58 0 bottom
CZ41  -  [C_0402]  304.33 44.79 0 bottom
CZ50  -  [C_0201]  165.52 85.97 90 bottom
CZ51  -  [C_0201]  165.86 81.91 90 bottom
CZ52  -  [C_0603]  166.63 80.23 0 bottom
CZ53  -  [C_0201]  170.28 88.23 180 bottom
CZ54  -  [C_0201]  173.83 83.22 0 bottom
CZ55  -  [C_0603]  171.13 88.55 0 bottom
CZ56  -  [C_0402]  174.94 87.59 90 bottom
CZ57  -  [C_0402]  165.56 79.34 180 bottom
CZ58  -  [C_0402]  165.56 80.23 180 bottom
CZ59  -  [C_0402]  170.52 89.68 90 bottom
CZ60  -  [C_0402]  171.41 89.67 90 bottom
CZ61  -  [C_0402]  262.49 23.74 0 top
CZ62  -  [C_0402]  270.55 26.82 90 top
CZ63  -  [C_0402]  269.67 26.82 90 top
CZ64  -  [C_0201]  266.46 25.48 270 top
CZ66  -  [C_0201]  264.28 25.53 270 top
CZ67  -  [C_0201]  265.8 25.46 270 top
CZ68  -  [C_0201]  270.96 29.23 0 top
CZ69  -  [C_0402]  267.18 25.47 270 top
CZ71  -  [C_0402]  263.51 25.53 270 top
CZ72  -  [C_0402]  265.03 25.46 270 top
CZ73  -  [C_0402]  270.87 29.99 0 top
CZ75  -  [C_0402]  165.61 85.26 270 bottom
CZ80  -  [C_0402]  250.46 25.34 0 top
CZ81  -  [C_0402]  250.48 24.41 0 top
CZ82  -  [C_0201]  244.53 34.18 270 bottom
CZ83  -  [C_0402]  247.55 26.36 180 top
CZ90  -  [C_0201]  247.56 27.11 180 top
CZ91  -  [C_0201]  245.86 27.01 270 top
CZ92  -  [C_0201]  245.29 27.03 270 top
CZ93  -  [C_0201]  251.87 34.3 180 top
CZ94  -  [C_0201]  154.09 115.63 270 top
CZ100  -  [C_0402]  132.78 107.12 270 bottom
CZ101  -  [C_0201]  127.92 106.09 270 bottom
CZ102  -  [C_0402]  176.9 44.66 90 top
CZ103  -  [C_0201]  177.57 46.34 180 top
CZ104  -  [C_0402]  187.84 52.04 0 top
CZ105  -  [C_0402]  129.05 104.11 180 bottom
CZ106  -  [C_0201]  131.61 100.18 0 bottom
CZ109  -  [C_0402]  300.74 64 90 top
CZ110  -  [C_0402]  301.96 63.98 90 top
CZ111  -  [C_0201]  302.69 63.89 90 top
CZ112  -  [C_0201]  198.25 33.69 180 top
CZ113  -  [C_0402]  198 34.63 180 top
CZ114  -  [C_0402]  198 35.52 180 top
CZ115  -  [C_0201]  198.17 36.35 180 top
CZ116  -  [C_0201]  289.77 79.9 0 top
CZ117  -  [C_0402]  289.93 79.17 0 top
CZ118  -  [C_0402]  289.96 78.28 0 top
CZ119  -  [C_0201]  289.82 77.55 0 top
CZ120  -  [C_0201]  165.33 68.54 270 top
CZ121  -  [C_0402]  167.9 69.5 0 top
CZ122  -  [C_0201]  300 63.91 90 top
CZ124  -  [C_0402]  289.84 76.82 0 top
CZ125  -  [C_0201]  296.66 19.22 270 top
CZ126  -  [C_0402]  295.9 19.45 270 top
CZ127  -  [C_0402]  295.01 19.45 270 top
CZ128  -  [C_0201]  294.26 19.4 270 top
CZ197  -  [C_0402]  167.26 64.48 0 top
CZ198  -  [C_0402]  264.25 73.5 270 top
DA1  -  [L03ESDL5V0CC3-2_SOT23-3]  309.37 15.41 90 top
DA2  -  [L03ESDL5V0CC3-2_SOT23-3]  315.32 11.17 270 bottom
DA3  -  [L03ESDL5V0CC3-2_SOT23-3]  308.8 20.03 90 top
DA6  -  [L03ESDL5V0CC3-2_SOT23-3]  297.74 3.22 0 top
DA7  -  [L03ESDL5V0CC3-2_SOT23-3]  293.12 3.35 0 top
DA8  -  [RB751S40T1G_SOD523-2]  290.36 39.33 270 top
DE1  -  [RB751S40T1G_SOD523-2]  183.35 77.72 90 bottom
DI1  -  [L05ESDL5V0NA-4_SLP2510P8-10-9]  22.21 30.37 270 top
DI2  -  [AZC199-02SPR7G_SOT23-3]  24.98 24.09 270 bottom
DI3  -  [AZC199-02SPR7G_SOT23-3]  25.37 37.3 270 bottom
DI4  -  [L05ESDL5V0NA-4_SLP2510P8-10-9]  304.89 65.77 90 bottom
DI5  -  [AZC199-02SPR7G_SOT23-3]  306.99 75.41 90 top
DI6  -  [L05ESDL5V0NA-4_SLP2510P8-10-9]  22.1 41.31 90 top
DT1  -  [1N4148WS-7-F_SOD323-2]  18.16 93.06 180 top
DT2  -  [1N4148WS-7-F_SOD323-2]  33.63 18.99 90 bottom
DT3  -  [1N4148WS-7-F_SOD323-2]  35.36 21.38 270 bottom
DT4  -  [L30ESD24VC3-2_SOT23-3]  11.53 79.79 180 bottom
DT5  -  [ESD8011MUT5G_X3DFN2-2-S]  11.71 92.61 90 top
DT6  -  [ESD8011MUT5G_X3DFN2-2-S]  11.71 91.89 270 top
DT7  -  [ESD8011MUT5G_X3DFN2-2-S]  12.57 90.38 90 top
DT8  -  [ESD8011MUT5G_X3DFN2-2-S]  14.63 87.33 90 top
DT9  -  [ESD8011MUT5G_X3DFN2-2-S]  11.64 86.7 90 top
DT10  -  [ESD8011MUT5G_X3DFN2-2-S]  11.64 85.99 270 top
DT11  -  [ESD8011MUT5G_X3DFN2-2-S]  13.87 89.75 90 top
DT12  -  [ESD8011MUT5G_X3DFN2-2-S]  13.87 89.03 270 top
DT13  -  [ESD8011MUT5G_X3DFN2-2-S]  11.71 92.61 90 bottom
DT14  -  [ESD8011MUT5G_X3DFN2-2-S]  11.71 91.89 270 bottom
DT15  -  [ESD8011MUT5G_X3DFN2-2-S]  12.6 90.38 90 bottom
DT16  -  [ESD8011MUT5G_X3DFN2-2-S]  14.63 87.33 90 bottom
DT17  -  [ESD8011MUT5G_X3DFN2-2-S]  11.64 85.99 270 bottom
DT18  -  [ESD8011MUT5G_X3DFN2-2-S]  11.64 86.7 90 bottom
DT19  -  [ESD8011MUT5G_X3DFN2-2-S]  13.87 89.03 270 bottom
DT20  -  [ESD8011MUT5G_X3DFN2-2-S]  13.87 89.75 90 bottom
DV1  -  [BAT54CW_SOT323-3]  65.03 112.87 0 top
DV2  -  [BAT54CW_SOT323-3]  67.3 110.34 0 top
DV3  -  [BAT54CW_SOT323-3]  71.06 107.33 0 top
DV4  -  [AZC199-02SPR7G_SOT23-3]  93.23 113.47 180 top
DV7  -  [ESD8011MUT5G_X3DFN2-2-S]  53.18 111.26 270 bottom
DV8  -  [ESD8011MUT5G_X3DFN2-2-S]  53.18 111.93 90 bottom
DZ1  -  [RB751S40T1G_SOD523-2]  280.72 49.6 0 top
DZ2  -  [RB751S40T1G_SOD523-2]  282.13 48.44 180 top
DZ5  -  [RB751S40T1G_SOD523-2]  263.11 70.41 90 top
DZ6  -  [RB751S40T1G_SOD523-2]  269.03 70.33 90 top
DZ7  -  [RB751S40T1G_SOD523-2]  259.13 26.09 180 bottom
FD1  -  [FIDUCIAL_C40M80]  42.6 113.15 180 bottom
FD2  -  [FIDUCIAL_C40M80]  319.76 3.14 180 bottom
FD3  -  [FIDUCIAL_C40M80]  318.34 3.47 0 top
FD4  -  [FIDUCIAL_C40M80]  41.38 113.18 0 top
H1  -  [H_3P3]  96.45 89.05 180 bottom
H2  -  [H_3P3]  155.55 66.55 180 bottom
H3  -  [H_3P3]  96.45 66.55 180 bottom
H4  -  [H_3P3]  155.55 89.05 180 bottom
H5  -  [H_1P0N]  106.55 90.76 0 top
H6  -  [H_1P0N]  147.67 67.65 0 top
H7  -  [H_3P2]  255 44.55 0 top
H8  -  [H_3P2]  271.2 111.35 0 top
H9  -  [H_2P3-G]  5.55 98.3 0 top
H10  -  [H_2P3-G]  5.55 81.4 0 top
H12  -  [H_2P3-G]  12.05 98.3 0 top
H14  -  [H_2P3-G]  44.8 11.2 0 top
H15  -  [H_2P3-G]  51.7 116.7 0 top
H17  -  [H_3P7-G]  48.65 18.4 0 top
H18  -  [H_3P7-G]  283.7 21.3 0 top
H19  -  [H_2P3-G]  292.6 14.6 0 top
H21  -  [H_2P3-G]  304.2 108.2 0 top
H22  -  [H_2P3-G]  260.2 116.7 0 top
H23  -  [H_2P5-G]  4.1 8.55 0 top
H24  -  [H_4P7X3P7-G]  63.4 20.85 0 top
H25  -  [H_4P7X3P7-G]  187.72 21.6 0 top
H26  -  [H_2P5-G]  322.3 8.55 0 top
H27  -  [H_2P5N]  314.2 27.4 0 top
H28  -  [H_5P0X4P0-G]  162.7 115.2 0 top
H29  -  [H_3P5X2P5N]  125.71 22.2 0 top
H30  -  [H_3P7-G]  253.4 69.25 0 top
H31  -  [H_3P7-G]  192.7 102.55 0 top
H34  -  [H_3P5X2P5-G]  11.95 11.45 0 top
JAPS1  -  [ACES_50506-01841-P01_18P]  312.35 103.4 0 bottom
JDB1  -  [ACES_50506-00641-P01_6P]  26.15 44.81 180 bottom
JDEG1  -  [HB_A531015-SCHR21_10P]  303.01 73.5 180 bottom
JDIMM1  -  [LCN_DAN05-Q0406-0103_260P]  46.32 33.1 180 bottom
JDIMM2  -  [LCN_DAN05-Q0406-0103_260P]  125.42 36.1 180 bottom
JEDP1  -  [ACES_50398-04041-001_40P]  58.7 117.4 0 bottom
JESPI  -  [ACES_50506-01041-P01_10P]  223.41 38.56 0 bottom
JFAN1  -  [ACES_50271-0040N-001_4P]  184.85 71.87 270 bottom
JHDMI1  -  [ACON_HMRBL-A41L0F_19P-T]  11.55 63.8 90 bottom
JHP1  -  [SINGA_2SJ3095-085111F_6P]  313.7 23.8 90 bottom
JIR1  -  [E-T_4251K-F06N-40L_6P]  104.15 116.25 180 bottom
JKBTP1  -  [CVILU_CF5020FD0RK-05-NH_20P-T]  252.85 27.11 180 bottom
JLED1  -  [ACES_50209-0060N-P01_6P]  314.69 7.77 180 bottom
JLOM1  -  [SANTA_130470-19_13P-T]  310.08 82.88 270 bottom
JNGFF1  -  [LCN_DAN05-67306-0100_75P]  288.52 35.3 90 bottom
JNGFF2  -  [BELLW_80149-3221_67P]  261.95 65.82 0 bottom
JNGFF3  -  [LOTES_APCI0170-P001A_75P]  38.35 16.45 180 bottom
JRTC1  -  [ACES_50271-0020N-001_2P]  305.85 19 180 bottom
JSD1  -  [T-SOL_158-1240902600_23P-T]  312.25 42.08 90 top
JSIM1  -  [JAE_SF51S006V4DR1000Q_8P]  310.93 44.02 270 bottom
JSPI1  -  [E-T_6705K-Y20N-00L_20P]  169.39 77.23 180 bottom
JSPK1  -  [ACES_50271-0040N-001_4P]  294.3 9.8 180 bottom
JTAG1  -  [SHORTPADS]  264.48 49.36 180 top
JTS1  -  [ACES_50209-0060N-P01_6P]  94.84 117.23 180 bottom
JUART1  -  [CVILU_CI1804M1VRA-NH_4P]  164.25 68.24 90 bottom
JUSB1  -  [ACON_TCRA2-9U1U93_9P-T]  310.46 58.1 270 bottom
JUSB2  -  [C-K_26230A-8K1A-02_9P-T]  15.95 29.15 90 bottom
JUSB3  -  [C-K_26230A-8K1A-02_9P-T]  15.95 48.65 90 bottom
JUSBC1  -  [JAE_DX07B024XJ1R1300_24P]  7.81 92.6 270 top
JUSH1  -  [CVILU_CF5026FD0RK-05-NH_26P-T]  275.15 27.11 180 bottom
JXDP1  -  [E-T_6601K-Y61N-04L_61P]  88.81 101.79 180 bottom
LA5  -  [MURAT_BLM15PX600SN1D_2P]  304.5 25.79 270 top
LA6  -  [MURAT_BLM15PX330SN1D_2P]  300.99 8.77 270 top
LA7  -  [MURAT_BLM15PX330SN1D_2P]  299.75 8.76 270 top
LA8  -  [MURAT_BLM15PX330SN1D_2P]  295.91 8.79 270 top
LA9  -  [MURAT_BLM15PX330SN1D_2P]  294.74 8.81 270 top
LA10  -  [MURAT_BLM15PX330SN1D_2P]  303.24 18.9 0 top
LA11  -  [MURAT_BLM15PX330SN1D_2P]  303.25 20.59 0 top
LA12  -  [MURAT_BLM15PX600SN1D_2P]  294.77 28.92 180 top
LA13  -  [TAI-T_HCB2012VF-601T20_2P]  297.84 39.27 180 top
LA14  -  [MURAT_BLM15PX600SN1D_2P]  295.08 37.37 180 top
LC1  -  [MURAT_BLM15GA750SN1D_2P]  136.38 74.25 180 top
LC2  -  [MURAT_BLM15GA750SN1D_2P]  148.66 96.3 180 top
LED3  -  [LED_LTW-C193DC-C_2P]  317.5 110.25 180 top
LI3  -  [PANAS_EXC24CQ900U_4P]  23.52 19.95 0 bottom
LI4  -  [PANAS_EXC24CQ900U_4P]  23.25 34.31 270 bottom
LI7  -  [PANAS_EXC24CQ900U_4P]  298.53 68.81 90 top
LI8  -  [INPAQ_HCM2012GA900AE_4P]  263.22 60.12 90 top
LI9  -  [INPAQ_HCM2012GA900AE_4P]  291.14 32.85 90 bottom
LI16  -  [INPAQ_HCM2012GA900AE_4P]  276.2 68.15 180 top
LI17  -  [INPAQ_HCM2012GA900AE_4P]  276.19 70.06 180 top
LL1  -  [TAIYO_BRC2012T4R7MD_2P]  274.55 87.62 0 top
LT1  -  [MAG_MND-04ABIR60M-XGL_2P]  22.5 78.61 180 bottom
LT2  -  [MURAT_LQM18NN1R0K00D_2P]  17.78 85.69 270 top
LV1  -  [MURAT_BLM15PX221SN1D_2P]  66.12 114.27 270 top
LV3  -  [TAIYO_MCF12102G900-T_4P]  17.53 62.59 180 bottom
LV6  -  [TAIYO_MCF12102G900-T_4P]  17.5 66.31 180 bottom
LV9  -  [TAIYO_MCF12102G900-T_4P]  17.52 64.53 180 bottom
LV12  -  [TAIYO_MCF12102G900-T_4P]  17.55 68.24 180 bottom
LV27  -  [PANAS_EXC24CQ900U_4P]  90.72 108.79 225 top
LV31  -  [MURAT_LQG15HN12NJ02D_2P]  17.37 61.87 180 bottom
LV32  -  [MURAT_LQG15HN12NJ02D_2P]  17.37 62.75 180 bottom
LV33  -  [MURAT_LQG15HN12NJ02D_2P]  17.34 65.6 180 bottom
LV34  -  [MURAT_LQG15HN12NJ02D_2P]  17.34 66.47 180 bottom
LV35  -  [MURAT_LQG15HN12NJ02D_2P]  17.34 63.81 180 bottom
LV36  -  [MURAT_LQG15HN12NJ02D_2P]  17.35 64.68 180 bottom
LV37  -  [MURAT_LQG15HN12NJ02D_2P]  17.39 67.54 180 bottom
LV38  -  [MURAT_LQG15HN12NJ02D_2P]  17.38 68.41 180 bottom
LZ1  -  [PANAS_EXC24CQ900U_4P]  51.03 111.32 270 bottom
NOREF  -  []  253.4 69.25 0 top
NOREF#2  -  []  296.61 96.23 0 top
NOREF#3  -  []  304.2 108.2 0 top
NOREF#4  -  []  -47.05 74.91 0 top
NOREF#5  -  []  271.2 111.35 0 top
NOREF#6  -  []  292.6 14.6 0 top
NOREF#7  -  []  48.65 18.4 135 top
NOREF#8  -  []  63.4 20.85 0 top
NOREF#9  -  []  96.45 66.55 0 top
NOREF#10  -  []  5.55 81.4 90 top
NOREF#11  -  []  12.05 98.3 0 top
NOREF#12  -  []  187.72 21.6 0 top
NOREF#13  -  []  5.55 98.3 0 top
NOREF#14  -  []  283.7 21.3 0 top
NOREF#15  -  []  255 44.55 0 top
NOREF#16  -  []  322.3 8.55 0 top
NOREF#17  -  []  192.7 102.55 0 top
NOREF#18  -  []  155.55 89.05 0 top
NOREF#19  -  []  98.14 -18.7 0 top
NOREF#20  -  []  259.53 98.46 0 top
NOREF#21  -  []  30.85 -40.83 0 top
NOREF#22  -  []  281.18 109.38 0 top
NOREF#23  -  []  44.8 11.2 0 top
NOREF#24  -  []  155.55 66.55 0 top
NOREF#25  -  []  162.7 115.2 90 top
NOREF#26  -  []  -67.82 40.93 0 top
NOREF#27  -  []  96.45 89.05 0 top
NOREF#28  -  []  4.1 8.55 0 top
NOREF#29  -  []  260.2 116.7 180 bottom
NOREF#30  -  []  -56.96 37.81 180 bottom
NOREF#31  -  []  -154.68 73.31 180 bottom
NOREF#32  -  []  51.7 116.7 180 bottom
PBATT1  -  [DEREN_40-42251-01001RHF_10P-T]  218.25 32.05 180 bottom
PC1  -  [C_0402]  210.06 35.27 270 bottom
PC2  -  [C_0402]  310.78 9.51 90 top
PC3  -  [C_0603]  308.94 9.38 270 top
PC4  -  [C_0603]  47.97 87.53 180 bottom
PC5  -  [C_0603]  47.32 105.2 0 bottom
PC6  -  [C_0603]  56.9 100.97 180 bottom
PC7  -  [C_0603]  52.55 100.42 90 bottom
PC8  -  [C_0805]  44.23 91.94 180 bottom
PC9  -  [C_0402]  33.93 111.44 0 top
PC10  -  [C_0402]  45.97 66.53 270 bottom
PC11  -  [C_0603]  39.92 68.27 180 bottom
PC100  -  [C_0402]  239.13 29.94 90 bottom
PC102  -  [C_0603]  230.33 28.94 0 bottom
PC103  -  [C_0402]  240.15 29.94 90 bottom
PC104  -  [C_0603]  239.46 28.86 270 bottom
PC105  -  [C_0805]  237.95 28.85 270 bottom
